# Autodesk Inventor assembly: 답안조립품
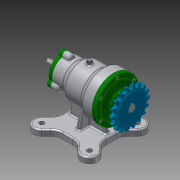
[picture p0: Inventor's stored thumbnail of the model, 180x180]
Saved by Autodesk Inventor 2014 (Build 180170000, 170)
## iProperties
Created: 2017-03
Part Number: 답안조립품
Document SubType Name: Assembly
Designer: user
Author: user
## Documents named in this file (14)
- C:\Users\user\Desktop\470308V1001\답안조립품.iam
- C:\Users\user\Desktop\470308V1001\본체.ipt
- C:\Users\user\Desktop\470308V1001\뒤커버.ipt
- C:\Users\user\Desktop\470308V1001\앞커버.ipt
- C:\Users\user\Desktop\470308V1001\볼트 M4 x 12.ipt
- C:\Users\user\Desktop\470308V1001\오일 실 10 20 7.ipt
- C:\Users\user\Desktop\470308V1001\오일 실 17 30 8.ipt
- C:\Users\user\Desktop\470308V1001\볼트 M5 x 10.ipt
- 볼트 M5 x 10.ipt
- C:\Users\user\Desktop\470308V1001\베어링-6203.ipt
- C:\Users\user\Desktop\470308V1001\베어링-6200.ipt
- C:\Users\user\Desktop\470308V1001\축.ipt
- C:\Users\user\Desktop\470308V1001\키5x5.ipt
- C:\Users\user\Desktop\470308V1001\스프로킷.ipt
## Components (9 placed, 1 different names)
1. ISO 4762 M4 x 12:1
2. ISO 4762 M4 x 12:2
3. ISO 4762 M4 x 12:3
4. ISO 4762 M4 x 12:4
5. ISO 4762 M4 x 12:5
6. ISO 4762 M4 x 12:6
7. ISO 4762 M4 x 12:7
8. ISO 4762 M4 x 12:8
9. ISO 4762 M4 x 12:9
